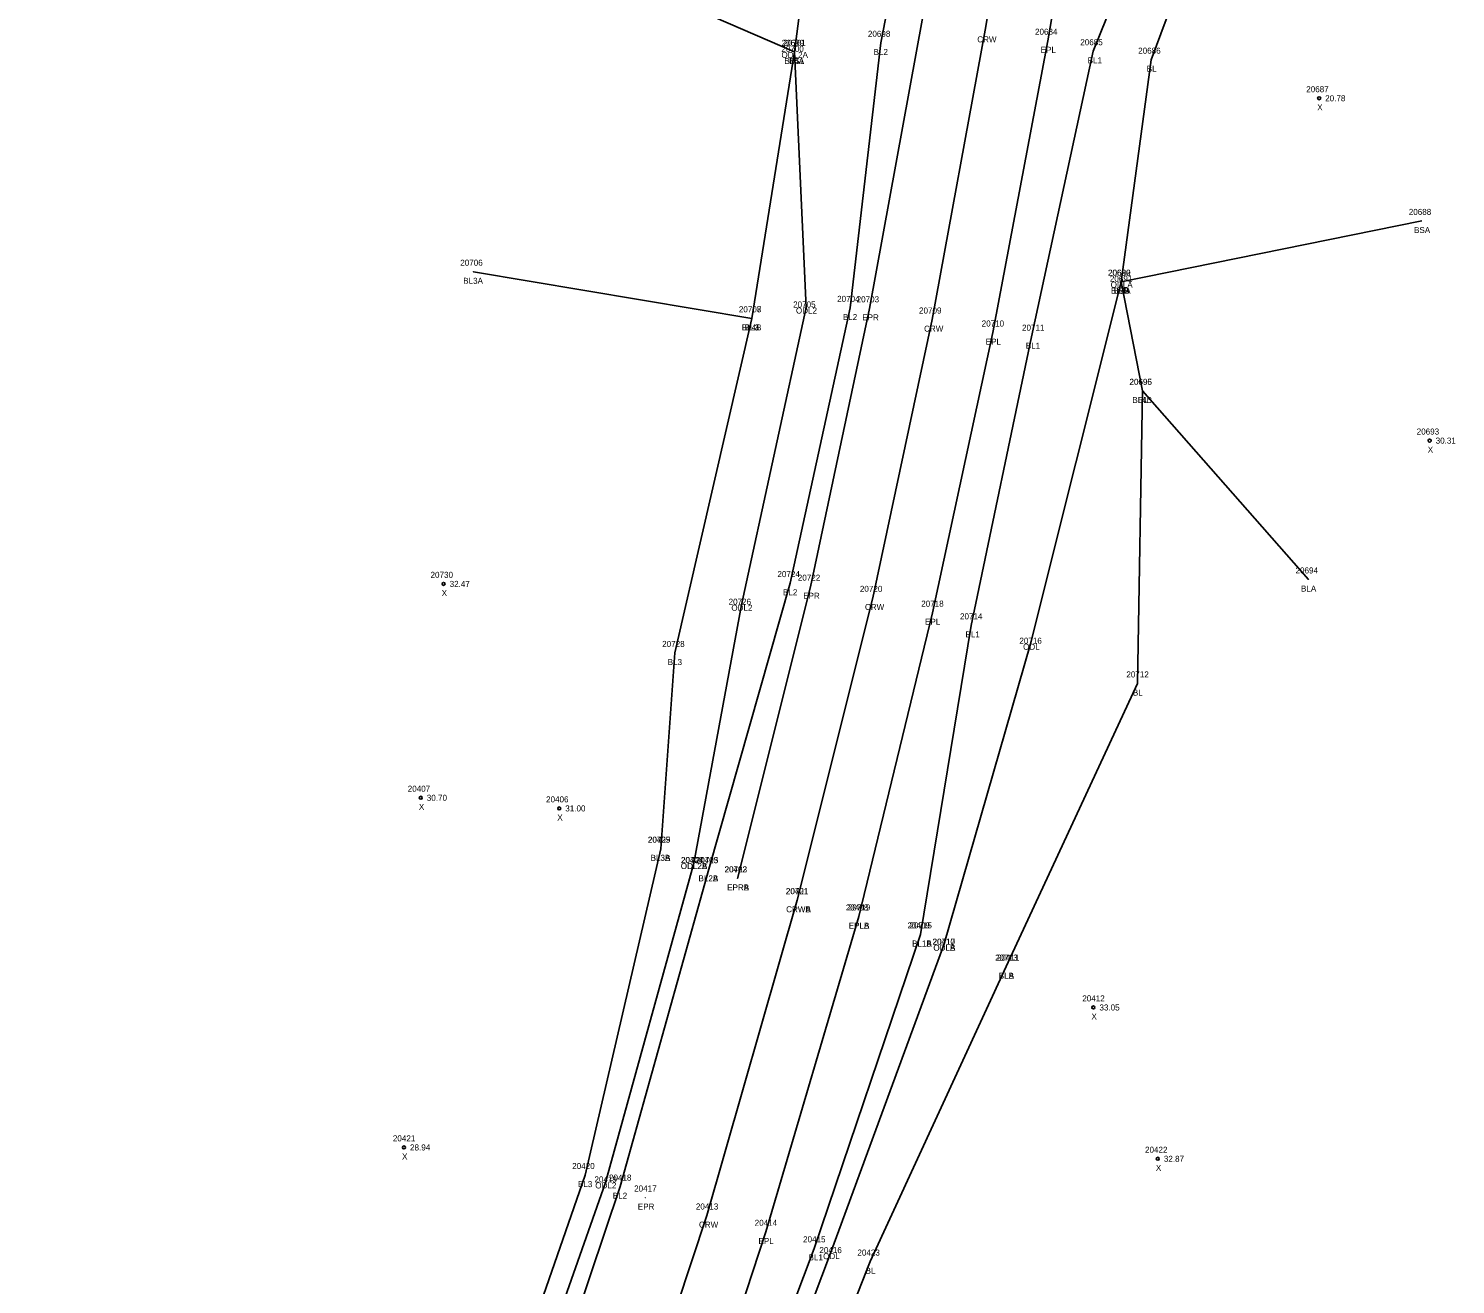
# Model space of a CAD drawing. Extents: x 2432729 to 2433340, y 684958 to 688103.
# Drawn here: x 2432940.1 to 2433176.5, y 685627 to 685835 of the extents above; entities that cross this region are included whole.
import ezdxf

# ---------------------------------------------------------------- set-up
doc = ezdxf.new("R2010")
doc.units = 0
for name, color, linetype in [('RD_DTM_BkLn1', 7, 'Continuous'), ('RD_DTM_BkLn2', 7, 'Continuous'), ('RD_EX_H2O', 7, 'Continuous'), ('RD_EX_H2O_txCode', 7, 'Continuous'), ('RD_EX_Road', 7, 'Continuous'), ('RD_EX_Road_txCode', 7, 'Continuous'), ('RD_Sketch8', 7, 'Continuous'), ('RD_SMD_Locator', 7, 'Continuous'), ('RD_SMD_Misc', 7, 'Continuous')]:
    doc.layers.add(name, color=color, linetype=linetype)

msp = doc.modelspace()

# ---------------------------------------------------------------- linework, layer by layer
at = {"layer": 'RD_DTM_BkLn1'}
for p, q in [((2433067.01, 685831.1), (2433059.94, 685786.97)), ((2433121.08, 685793.04), (2433124.62, 685774.96))]:
    msp.add_line(p, q, dxfattribs=at)
for points in [[(2433103.52, 685947.31), (2433081.29, 685832.59), (2433076.2, 685788.7), (2433066.28, 685743.12), (2433052.78, 685695.75)], [(2433130.23, 685940.32), (2433158.37, 685928.4), (2433154.38, 685925.19), (2433116.47, 685831.2), (2433106.22, 685783.93), (2433096.24, 685736.13), (2433087.86, 685684.95)], [(2433164.1, 685935.07), (2433164.23, 685926.52), (2433158.2, 685916.25), (2433126.08, 685829.8), (2433121.08, 685793.04)], [(2433115.16, 685931.88), (2433098.58, 685834.67), (2433089.77, 685786.77), (2433079.97, 685740.68), (2433067.41, 685690.62)], [(2433013.83, 685794.69), (2433059.94, 685786.97), (2433047.2, 685731.56), (2433044.85, 685699.14)], [(2433152.12, 685743.73), (2433124.62, 685774.96), (2433123.78, 685726.51), (2433102.05, 685679.62)], [(2433044.85, 685699.14), (2433032.33, 685645.11), (2433014.81, 685594.7), (2432998.67, 685551.2), (2432976.89, 685500.47), (2432957.99, 685451.85), (2432944.14, 685420.07)], [(2433052.78, 685695.75), (2433038.11, 685643.19), (2433020.67, 685591.28), (2433004.11, 685548.28), (2432984.11, 685498.02), (2432963.5, 685449.48), (2432949.33, 685418.54), (2432944.14, 685420.07)], [(2433067.41, 685690.62), (2433052.49, 685638.4), (2433035.04, 685585.7), (2433018.41, 685541.16), (2432999.85, 685493.3), (2432978.77, 685442.62), (2432938.71, 685349.86), (2432898.27, 685257.39), (2432861.69, 685174.74), (2432859.51, 685169.85), (2432818.13, 685076.09), (2432777.09, 684983.43)], [(2433087.86, 685684.95), (2433070.24, 685632.97), (2433050.83, 685581.32), (2433032.43, 685535.6), (2433015.06, 685486.22), (2432993.56, 685435.75), (2432952.83, 685343.93), (2432911.02, 685251.28), (2432891.52, 685205.36), (2432897.43, 685203.55)], [(2433102.05, 685679.62), (2433079.53, 685630.77), (2433059.07, 685578.75), (2433039.78, 685531.36), (2433020.13, 685482.85), (2432998.25, 685432.63), (2432957.4, 685341.66), (2432916.69, 685248.39), (2432897.43, 685203.55)]]:
    msp.add_lwpolyline(points, dxfattribs=at)
at = {"layer": 'RD_DTM_BkLn2'}
msp.add_line((2433170.86, 685803.1), (2433121.08, 685793.04), dxfattribs=at)
msp.add_lwpolyline([(2433090.75, 685956.18), (2433081.26, 685940.73), (2433067.01, 685831.1), (2433031.98, 685846.3)], dxfattribs=at)
at = {"layer": 'RD_EX_H2O'}
for points in [[(2433067.01, 685831.1), (2433068.92, 685788.77), (2433058.23, 685739.55), (2433050.34, 685696.78)], [(2433121.08, 685793.04), (2433106.09, 685733.09), (2433091.72, 685683.25)], [(2433050.34, 685696.78), (2433035.7, 685643.89), (2433017.64, 685592.53), (2433001.42, 685549.29), (2432980.66, 685498.68), (2432961.21, 685450.45), (2432948.33, 685421.39)], [(2433091.72, 685683.25), (2433072.97, 685632.18), (2433053.46, 685580.43), (2433036.38, 685533.4), (2433017.44, 685484.85), (2432996.16, 685434.2), (2432954.84, 685343.07), (2432912.85, 685250.04), (2432894.77, 685206.8)]]:
    msp.add_lwpolyline(points, dxfattribs=at)
at = {"layer": 'RD_EX_Road'}
for points in [[(2433104.8, 685933.95), (2433088.22, 685836.98), (2433079.44, 685788.63), (2433069.66, 685742.53), (2433057.55, 685694.23)], [(2433125.56, 685930.12), (2433108.96, 685832.94), (2433099.86, 685784.62), (2433089.82, 685738.23), (2433077.66, 685687.92)], [(2433077.66, 685687.92), (2433062.23, 685635.7), (2433044.84, 685582.68), (2433028.22, 685537.07), (2433009.68, 685489.83), (2432988.53, 685438.27), (2432948.62, 685345.62), (2432907.86, 685252.74), (2432887.37, 685205.96), (2432872.08, 685170.45), (2432827.85, 685071.69), (2432787.31, 684979.59)]]:
    msp.add_lwpolyline(points, dxfattribs=at)
at = {"layer": 'RD_SMD_Locator'}
for centre, radius in [((2433098.58, 685834.67), 0.001), ((2433081.29, 685832.59), 0.001), ((2433108.96, 685832.94), 0.001), ((2433067.01, 685831.1), 0.001), ((2433067.01, 685831.1), 0.001), ((2433067.01, 685831.1), 0.001), ((2433116.47, 685831.2), 0.001), ((2433126.08, 685829.8), 0.001), ((2433153.88, 685823.42), 0.25), ((2433170.86, 685803.1), 0.001), ((2433013.83, 685794.69), 0.001), ((2433121.08, 685793.04), 0.001), ((2433121.08, 685793.04), 0.001), ((2433121.08, 685793.04), 0.001), ((2433121.08, 685793.04), 0.001), ((2433068.92, 685788.77), 0.001), ((2433076.2, 685788.7), 0.001), ((2433079.44, 685788.63), 0.001), ((2433059.94, 685786.97), 0.001), ((2433059.94, 685786.97), 0.001), ((2433089.77, 685786.77), 0.001), ((2433099.86, 685784.62), 0.001), ((2433106.22, 685783.93), 0.001), ((2433124.62, 685774.96), 0.001), ((2433124.62, 685774.96), 0.001), ((2433172.17, 685766.73), 0.25), ((2433008.88, 685743), 0.25), ((2433066.28, 685743.12), 0.001), ((2433069.66, 685742.53), 0.001), ((2433152.12, 685743.73), 0.001), ((2433079.97, 685740.68), 0.001), ((2433058.23, 685739.55), 0.001), ((2433089.82, 685738.23), 0.001), ((2433096.24, 685736.13), 0.001), ((2433106.09, 685733.09), 0.001), ((2433047.2, 685731.56), 0.001), ((2433123.78, 685726.51), 0.001), ((2433005.1, 685707.58), 0.25), ((2433028.03, 685705.82), 0.25), ((2433044.85, 685699.14), 0.001), ((2433044.85, 685699.14), 0.001), ((2433050.34, 685696.78), 0.001), ((2433050.34, 685696.78), 0.001), ((2433052.78, 685695.75), 0.001), ((2433052.78, 685695.75), 0.001), ((2433057.55, 685694.23), 0.001), ((2433057.55, 685694.23), 0.001), ((2433067.41, 685690.62), 0.001), ((2433067.41, 685690.62), 0.001), ((2433077.66, 685687.92), 0.001), ((2433077.66, 685687.92), 0.001), ((2433087.86, 685684.95), 0.001), ((2433087.86, 685684.95), 0.001), ((2433091.72, 685683.25), 0.001), ((2433091.72, 685683.25), 0.001), ((2433102.05, 685679.62), 0.001), ((2433102.05, 685679.62), 0.001), ((2433116.49, 685672.86), 0.25), ((2433002.32, 685649.68), 0.25), ((2433127.16, 685647.8), 0.25), ((2433032.33, 685645.11), 0.001), ((2433035.7, 685643.89), 0.001), ((2433038.11, 685643.19), 0.001), ((2433042.27, 685641.38), 0.001), ((2433052.49, 685638.4), 0.001), ((2433062.23, 685635.7), 0.001), ((2433070.24, 685632.97), 0.001), ((2433072.97, 685632.18), 0.001), ((2433079.53, 685630.77), 0.001)]:
    msp.add_circle(centre, radius, dxfattribs=at)

# ---------------------------------------------------------------- texts
at = {"layer": 'RD_EX_H2O_txCode'}
for s, p in [('20700', (2433064.82, 685831.1)), ('ODL2A', (2433064.83, 685830.1)), ('20691', (2433119.22, 685793.04)), ('ODLA', (2433119.35, 685792.04)), ('20705', (2433066.77, 685788.77)), ('ODL2', (2433067.23, 685787.77)), ('20726', (2433056.08, 685739.55)), ('ODL2', (2433056.53, 685738.55)), ('20716', (2433104.23, 685733.09)), ('ODL', (2433104.85, 685732.09)), ('20404', (2433048.18, 685696.78)), ('20727', (2433048.22, 685696.78)), ('ODL2A', (2433048.15, 685695.78)), ('ODL2B', (2433048.17, 685695.78)), ('20410', (2433089.84, 685683.25)), ('20717', (2433089.88, 685683.25)), ('ODLA', (2433089.98, 685682.25)), ('ODLB', (2433090, 685682.25)), ('20419', (2433033.86, 685643.89)), ('ODL2', (2433034, 685642.89)), ('20416', (2433071.11, 685632.18)), ('ODL', (2433071.73, 685631.18))]:
    msp.add_text(s, height=1, dxfattribs=at).set_placement(p)
at = {"layer": 'RD_EX_Road_txCode'}
for s, p in [('20684', (2433106.82, 685833.94)), ('EPL', (2433107.76, 685830.94)), ('20703', (2433077.28, 685789.63)), ('EPR', (2433078.21, 685786.63)), ('20710', (2433097.99, 685785.62)), ('EPL', (2433098.66, 685782.62)), ('20722', (2433067.54, 685743.53)), ('EPR', (2433068.43, 685740.53)), ('20718', (2433087.98, 685739.23)), ('EPL', (2433088.61, 685736.23)), ('20402', (2433055.39, 685695.23)), ('20723', (2433055.43, 685695.23)), ('EPRA', (2433055.83, 685692.23)), ('EPRB', (2433055.85, 685692.23)), ('20408', (2433075.5, 685688.92)), ('20719', (2433075.82, 685688.92)), ('EPLA', (2433075.96, 685685.92)), ('EPLB', (2433075.98, 685685.92)), ('20417', (2433040.44, 685642.38)), ('EPR', (2433041.04, 685639.38)), ('20414', (2433060.4, 685636.7)), ('EPL', (2433061.03, 685633.7))]:
    msp.add_text(s, height=1, dxfattribs=at).set_placement(p)
at = {"layer": 'RD_Sketch8'}
for s, p in [('20687', (2433151.74, 685824.42)), ('20.78', (2433154.88, 685822.92)), ('X', (2433153.56, 685821.42)), ('20693', (2433170.03, 685767.73)), ('30.31', (2433173.17, 685766.23)), ('X', (2433171.86, 685764.73)), ('20730', (2433006.72, 685744)), ('32.47', (2433009.88, 685742.5)), ('X', (2433008.56, 685741)), ('20407', (2433002.94, 685708.58)), ('30.70', (2433006.1, 685707.08)), ('20406', (2433025.85, 685706.82)), ('X', (2433004.79, 685705.58)), ('X', (2433027.71, 685703.82)), ('31.00', (2433029.03, 685705.32)), ('20412', (2433114.65, 685673.86)), ('X', (2433116.17, 685670.86)), ('33.05', (2433117.49, 685672.36)), ('20421', (2433000.48, 685650.68)), ('X', (2433002, 685647.68)), ('28.94', (2433003.32, 685649.18)), ('20422', (2433125.04, 685648.8)), ('32.87', (2433128.16, 685647.3)), ('X', (2433126.84, 685645.8))]:
    msp.add_text(s, height=1, dxfattribs=at).set_placement(p)
at = {"layer": 'RD_SMD_Misc'}
for s, p in [('20698', (2433079.15, 685833.59)), ('20699', (2433064.87, 685832.1)), ('20701', (2433065.14, 685832.1)), ('CRW', (2433097.26, 685832.67)), ('20685', (2433114.32, 685832.2)), ('BL4A', (2433065.32, 685829.1)), ('BS1', (2433066.07, 685829.1)), ('BL2', (2433080.09, 685830.59)), ('BL1', (2433115.54, 685829.2)), ('20686', (2433123.91, 685830.8)), ('BL', (2433125.32, 685827.8)), ('20688', (2433168.72, 685804.1)), ('BSA', (2433169.59, 685801.1)), ('20706', (2433011.64, 685795.69)), ('20690', (2433118.9, 685794.04)), ('20689', (2433118.94, 685794.04)), ('20692', (2433118.94, 685794.04)), ('BL3A', (2433012.13, 685792.69)), ('BL4A', (2433119.39, 685791.04)), ('BSB', (2433119.83, 685791.04)), ('BLB', (2433119.85, 685791.04)), ('20704', (2433074.05, 685789.7)), ('20707', (2433057.78, 685787.97)), ('20708', (2433057.78, 685787.97)), ('BL2', (2433075, 685786.7)), ('20709', (2433087.61, 685787.77)), ('BL4B', (2433058.26, 685784.97)), ('BL3', (2433058.73, 685784.97)), ('CRW', (2433088.45, 685784.77)), ('20711', (2433104.67, 685784.93)), ('BL1', (2433105.3, 685781.93)), ('20696', (2433122.45, 685775.96)), ('20695', (2433122.48, 685775.96)), ('BL4B', (2433122.94, 685772.96)), ('BL', (2433123.86, 685772.96)), ('20724', (2433064.16, 685744.12)), ('20694', (2433149.97, 685744.73)), ('20720', (2433077.82, 685741.68)), ('BLA', (2433150.87, 685741.73)), ('BL2', (2433065.08, 685741.12)), ('CRW', (2433078.66, 685738.68)), ('20714', (2433094.4, 685737.13)), ('20728', (2433045.08, 685732.56)), ('BL1', (2433095.31, 685734.13)), ('BL3', (2433045.99, 685729.56)), ('20712', (2433121.95, 685727.51)), ('BL', (2433123.03, 685724.51)), ('20405', (2433042.69, 685700.14)), ('20729', (2433042.73, 685700.14)), ('BL3A', (2433043.15, 685697.14)), ('BL3B', (2433043.17, 685697.14)), ('20403', (2433050.62, 685696.75)), ('20725', (2433050.66, 685696.75)), ('BL2A', (2433051.09, 685693.75)), ('BL2B', (2433051.1, 685693.75)), ('20401', (2433065.54, 685691.62)), ('20721', (2433065.58, 685691.62)), ('CRWA', (2433065.61, 685688.62)), ('CRWB', (2433065.62, 685688.62)), ('20409', (2433085.7, 685685.95)), ('20715', (2433086.03, 685685.95)), ('BL1A', (2433086.45, 685682.95)), ('BL1B', (2433086.47, 685682.95)), ('20713', (2433100.22, 685680.62)), ('20411', (2433100.5, 685680.62)), ('BLA', (2433100.81, 685677.62)), ('BLB', (2433100.82, 685677.62)), ('20420', (2433030.18, 685646.11)), ('BL3', (2433031.13, 685643.11)), ('20418', (2433036.27, 685644.19)), ('BL2', (2433036.9, 685641.19)), ('20413', (2433050.66, 685639.4)), ('CRW', (2433051.17, 685636.4)), ('20415', (2433068.41, 685633.97)), ('BL1', (2433069.32, 685630.97)), ('20423', (2433077.41, 685631.77)), ('BL', (2433078.77, 685628.77))]:
    msp.add_text(s, height=1, dxfattribs=at).set_placement(p)

doc.saveas('drawing.dxf')
